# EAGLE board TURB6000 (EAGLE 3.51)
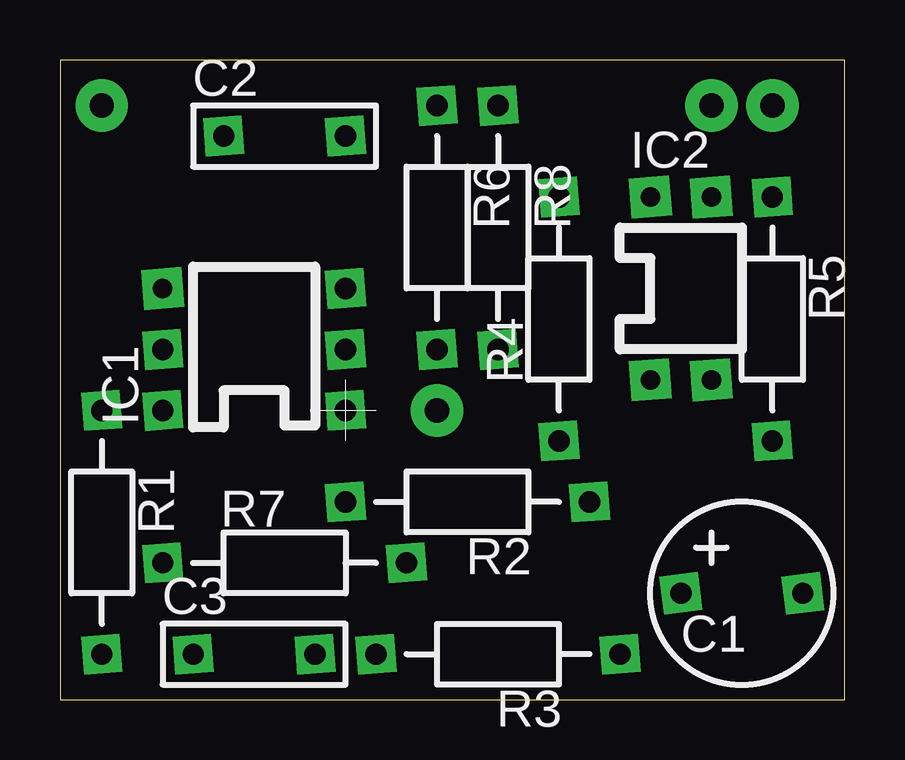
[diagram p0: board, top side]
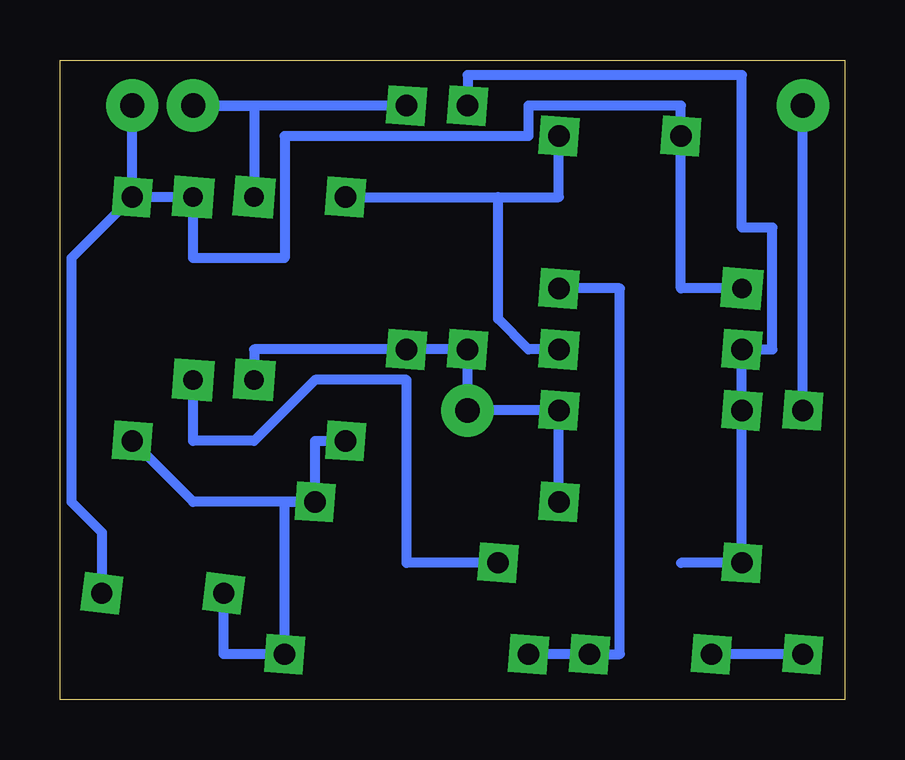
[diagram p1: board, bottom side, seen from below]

Size 32.69 x 26.66 mm. Coordinates in mm from the lower left corner, seen from the top.
Outline: 0,0 32.69,0 32.69,26.66 0,26.66 0,0
Copper layers used: Bottom

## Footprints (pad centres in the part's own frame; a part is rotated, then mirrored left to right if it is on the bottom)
P200RA = drill 0.889 pad 1.6 square:  0,0;  5.08,0
P200QA = drill 0.889 pad 1.6 square:  0,0;  5.08,0
L6 = drill 0.889 pad 1.6 square:  0,6.35;  2.54,6.35;  0,-1.27;  2.54,-1.27;  5.08,-1.27 | drill 0.813 pad 1.676 square:  5.08,6.35
L4 = drill 0.813 pad 1.676 square:  0,7.62;  2.54,7.62;  0,0;  2.54,0
ETSTIF = drill 1.016 pad 2.184 round: 1 0,0
P400IL = drill 0.889 pad 1.6 square:  0,0;  10.16,0

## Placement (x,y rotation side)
C1  2.2æF  [P200RA]  25.87,4.44 0 top
C2  47nF  [P200QA]  6.82,23.49 0 top
C3  22nF  [P200QA]  5.55,1.9 0 top
IC1  B621  [L6]  10.63,12.06 90 top
IC2  A302  [L4]  24.6,13.33 0 top
LS1  Input  [ETSTIF]  1.74,24.76 0 top
LS2  +5V (10)  [ETSTIF]  15.71,12.06 0 top
LS3  Ground (4)  [ETSTIF]  29.68,24.76 0 top
LS4  Proceed (9)  [ETSTIF]  27.14,24.76 0 top
R1  1k  [P400IL]  1.74,12.06 270 top
R2  4.7k  [P400IL]  22.06,8.25 180 top
R3  51k  [P400IL]  23.33,1.9 180 top
R4  51k  [P400IL]  20.79,10.79 90 top
R5  4.7k  [P400IL]  29.68,20.95 270 top
R6  12k  [P400IL]  15.71,24.76 270 top
R7  1k  [P400IL]  4.28,5.71 0 top
R8  12k  [P400IL]  18.25,24.76 270 top

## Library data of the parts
C1-C3 R1-R8 = DISCRETE
IC1 IC2 = ANALOG
LS1-LS4 = CONNEC

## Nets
+5V: IC1. IC2. LS2.1 R2. R6. R8.
GND: C1. C2. IC1. IC2. LS3.1 R5.
INPUT: LS1.1 R1.
N$1: C1. R2. R3. R4. R5.
N$2: C3. IC1. R3.
N$4: C3. R1.
N$5: C2. IC1. R4.
N$6: IC1. R6. R7.
N$12: IC2. R7.
PROCEED: IC2. LS4.1 R8.

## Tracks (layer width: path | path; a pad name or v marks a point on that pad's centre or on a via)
+5V
  Bottom 0.406: R2. 11.9,12.06 LS2.1 R6. | R8. 24.6,14.6 24.6,13.33 | R6. R8. | R6. R8. | R6. R8.
GND
  Bottom 0.406: 29.68,20.95 32.22,18.41 32.22,8.25 30.95,6.98 C1. | 29.68,20.95 LS3.1 29.68,20.95 | 29.68,20.95 27.14,20.95 27.14,18.41 23.33,18.41 23.33,23.49 13.17,23.49 13.17,24.76 6.82,24.76 6.82,23.49 6.82,17.14 4.28,17.14
INPUT
  Bottom 0.406: 1.74,12.06 LS1.1
N$1
  Bottom 0.406: 22.06,8.25 22.06,10.79 20.79,10.79 | 25.87,4.44 25.87,1.9 23.33,1.9 23.33,8.25 22.06,8.25 | 22.06,8.25 27.14,8.25 R5.
N$2
  Bottom 0.406: R3. C3. 9.36,1.9 9.36,17.14 IC1.
N$4
  Bottom 0.406: R1. 5.55,1.9
N$5
  Bottom 0.406: R4. 14.44,20.95 | 11.9,14.6 13.17,14.6 14.44,15.87 14.44,20.95 | 14.44,20.95 11.9,20.95 C2.
N$6
  Bottom 0.406: 15.71,24.76 15.71,26.03 4.28,26.03 4.28,19.68 3.01,19.68 3.01,14.6 4.28,14.6 4.28,12.06 4.28,5.71 6.82,5.71
N$12
  Bottom 0.406: R7. 18.25,5.71 18.25,13.33 22.06,13.33 24.6,10.79 27.14,10.79 IC2.
PROCEED
  Bottom 0.406: 24.6,20.95 24.6,24.76 LS4.1 18.25,24.76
